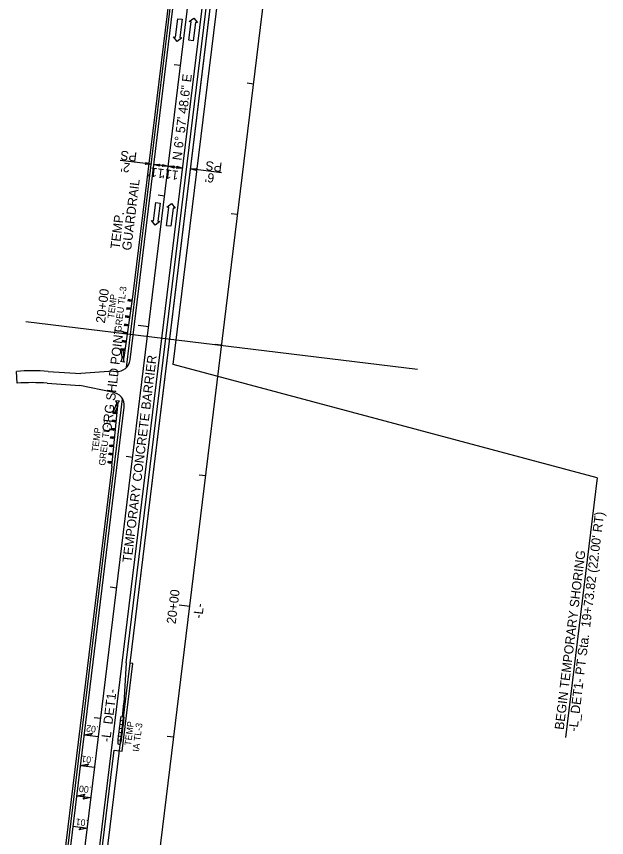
# Model space of a CAD drawing. Extents: x 473658 to 481584, y 489119 to 506230.
# Drawn here: x 481135 to 481584, y 489912 to 490536 of the extents above; entities that cross this region are included whole.
import ezdxf

# ---------------------------------------------------------------- set-up
doc = ezdxf.new("R2010")
doc.units = 0
for name, color, linetype in [('Exist Horizontal Alignment', 7, 'Continuous'), ('Exist Structure Minor Culvert Topo', 7, 'Continuous'), ('Exist Structure Minor Pipes CMP 60 Inch', 7, 'Continuous'), ('Exist Structure Minor Pipes RCP 12 Inch Leader', 7, 'Continuous'), ('Prop Conc Barrier', 7, 'Continuous'), ('Prop Dimension', 7, 'Continuous'), ('Prop EOT', 7, 'Continuous'), ('Prop Guardrail', 7, 'Continuous'), ('Prop Guardrail Anchor Unit CELL', 7, 'Continuous'), ('Prop Horizontal Alignment', 7, 'Continuous'), ('Prop Horizontal Alignment Direction Label', 7, 'Continuous'), ('Prop Horizontal Alignment Station Label', 7, 'Continuous'), ('Prop Horizontal Alignment Tick Label', 7, 'Continuous'), ('Prop Horizontal Alignment Tick Large', 7, 'Continuous'), ('Prop Horizontal Alignment Tick Small', 7, 'Continuous'), ('Prop Paved Shoulder', 7, 'Continuous'), ('Prop Shade Medium', 7, 'Continuous'), ('Prop Superelevation  Arrow CELL', 7, 'Continuous'), ('Prop Superelevation Label', 7, 'Continuous'), ('Scratch_Level_5', 7, 'Continuous'), ('Sheet Plan And Profile CELL', 7, 'Continuous'), ('Sheet Profile Grid Major CELL', 7, 'Continuous')]:
    doc.layers.add(name, color=color, linetype=linetype)

msp = doc.modelspace()

# ---------------------------------------------------------------- linework, layer by layer
at = {"layer": 'Exist Horizontal Alignment'}
for points in [[(481233.45, 490425.46), (481237.82, 490424.14), (481233.23, 490423.9), (481233.9, 490424.62)], [(481244.14, 490422.6), (481239.77, 490423.91), (481244.35, 490424.16), (481243.69, 490423.43)], [(481246.31, 490423.89), (481250.68, 490422.58), (481246.1, 490422.33), (481246.76, 490423.06)], [(481255.06, 490421.26), (481250.68, 490422.58), (481255.27, 490422.82), (481254.61, 490422.1)], [(481257.27, 490422.55), (481261.65, 490421.23), (481257.06, 490420.99), (481257.73, 490421.71)], [(481271.88, 490419.25), (481267.51, 490420.57), (481272.1, 490420.81), (481271.43, 490420.09)]]:
    msp.add_lwpolyline(points, close=True, dxfattribs=at)
at = {"layer": 'Exist Structure Minor Pipes CMP 60 Inch'}
msp.add_line((481254.45, 490271.98), (481344.18, 491006.64), dxfattribs=at)
at = {"layer": 'Exist Structure Minor Pipes RCP 12 Inch Leader'}
for p, q in [((481214.54, 490004.6), (481214.18, 490001.62)), ((481214.54, 490004.6), (481217.03, 490004.3)), ((481217.03, 490004.3), (481216.66, 490001.32)), ((481213.82, 489998.65), (481213.45, 489995.67)), ((481214.18, 490001.62), (481213.82, 489998.65)), ((481213.82, 489998.65), (481216.3, 489998.34)), ((481214.18, 490001.62), (481216.66, 490001.32)), ((481216.3, 489998.34), (481215.93, 489995.36)), ((481216.66, 490001.32), (481216.3, 489998.34)), ((481213.09, 489992.69), (481212.72, 489989.71)), ((481213.45, 489995.67), (481213.09, 489992.69)), ((481213.09, 489992.69), (481215.57, 489992.39)), ((481213.45, 489995.67), (481215.93, 489995.36)), ((481215.57, 489992.39), (481215.21, 489989.41)), ((481215.93, 489995.36), (481215.57, 489992.39)), ((481212.36, 489986.73), (481212.24, 489985.74)), ((481212.24, 489985.74), (481212.25, 489983.73)), ((481212.72, 489989.71), (481212.36, 489986.73)), ((481212.36, 489986.73), (481214.84, 489986.43)), ((481212.72, 489989.71), (481215.21, 489989.41)), ((481214.72, 489985.44), (481214.23, 489983.48)), ((481214.84, 489986.43), (481214.72, 489985.44)), ((481215.21, 489989.41), (481214.84, 489986.43)), ((481212.25, 489983.73), (481213.24, 489983.6)), ((481213.24, 489983.6), (481214.23, 489983.48))]:
    msp.add_line(p, q, dxfattribs=at)
at = {"layer": 'Prop Conc Barrier'}
for p, q in [((481218.72, 490045.39), (481336.24, 491007.62)), ((481218.72, 490045.39), (481217.03, 490014.62)), ((481215.78, 490004.45), (481217.03, 490014.62))]:
    msp.add_line(p, q, dxfattribs=at)
at = {"layer": 'Prop Dimension'}
for p, q in [((481237.78, 490424.16), (481214.22, 490427.03)), ((481261.6, 490421.23), (481239.77, 490423.91)), ((481291.01, 490417.64), (481267.51, 490420.57))]:
    msp.add_line(p, q, dxfattribs=at)
at = {"layer": 'Prop EOT'}
for p, q in [((481195.32, 489878.54), (481333.26, 491007.97)), ((481221.63, 490275.44), (481280.31, 490755.9)), ((481135.89, 490257.77), (481135.3, 490266.75)), ((481159.31, 490266.74), (481184.19, 490265.02)), ((481209.13, 490266.8), (481184.19, 490265.02)), ((481209.13, 490266.8), (481211.01, 490266.67)), ((481158.69, 490257.77), (481183.57, 490256.04)), ((481208.02, 490250.84), (481183.57, 490256.04)), ((481173.48, 489881.21), (481217.26, 490239.65))]:
    msp.add_line(p, q, dxfattribs=at)
for centre, radius, start, end in [((481211.7, 490276.65), 10, 266.04028, 353.03651), ((481147.26, 490092.66), 174.5, 86.04028, 93.92915), ((481147.26, 490092.66), 165.5, 86.04028, 93.93992), ((481207.33, 490240.87), 10, 353.03651, 86.04028)]:
    msp.add_arc(centre, radius, start, end, dxfattribs=at)
at = {"layer": 'Prop Guardrail'}
for p, q in [((481271.2, 490714.29), (481223.47, 490323.45)), ((481207.7, 490194.38), (481169.51, 489881.7))]:
    msp.add_line(p, q, dxfattribs=at)
at = {"layer": 'Prop Guardrail Anchor Unit CELL'}
for p, q in [((481223.47, 490323.45), (481216.87, 490277.16)), ((481220.14, 490321.35), (481220, 490320.36)), ((481220, 490320.36), (481221.62, 490321.14)), ((481223.11, 490320.93), (481220.14, 490321.35)), ((481221.48, 490320.15), (481220.14, 490321.35)), ((481221.62, 490321.14), (481221.48, 490320.15)), ((481221.48, 490320.15), (481223.11, 490320.93)), ((481221.62, 490321.14), (481222.97, 490319.94)), ((481223.11, 490320.93), (481222.97, 490319.94)), ((481219.2, 490315.12), (481219.05, 490314.13)), ((481219.05, 490314.13), (481220.71, 490314.91)), ((481222.22, 490314.69), (481219.2, 490315.12)), ((481220.57, 490313.92), (481219.2, 490315.12)), ((481222.97, 490319.94), (481220, 490320.36)), ((481220.71, 490314.91), (481220.57, 490313.92)), ((481222.22, 490314.69), (481220.57, 490313.92)), ((481220.71, 490314.91), (481222.08, 490313.7)), ((481222.97, 490319.94), (481221.48, 490320.15)), ((481218.31, 490308.88), (481218.17, 490307.89)), ((481218.17, 490307.89), (481219.82, 490308.67)), ((481221.33, 490308.45), (481218.31, 490308.88)), ((481219.68, 490307.68), (481218.31, 490308.88)), ((481222.08, 490313.7), (481219.05, 490314.13)), ((481219.82, 490308.67), (481219.68, 490307.68)), ((481221.33, 490308.45), (481219.68, 490307.68)), ((481219.82, 490308.67), (481221.19, 490307.46)), ((481217.43, 490302.64), (481217.29, 490301.65)), ((481217.29, 490301.65), (481218.94, 490302.43)), ((481220.44, 490302.22), (481217.43, 490302.64)), ((481218.8, 490301.44), (481217.43, 490302.64)), ((481221.19, 490307.46), (481218.17, 490307.89)), ((481218.94, 490302.43), (481218.8, 490301.44)), ((481220.44, 490302.22), (481218.8, 490301.44)), ((481218.94, 490302.43), (481220.3, 490301.23)), ((481220.44, 490302.22), (481220.3, 490301.23)), ((481216.44, 490296.42), (481216.3, 490295.43)), ((481216.3, 490295.43), (481218, 490296.2)), ((481219.55, 490295.98), (481216.44, 490296.42)), ((481217.86, 490295.21), (481216.44, 490296.42)), ((481220.3, 490301.23), (481217.29, 490301.65)), ((481218, 490296.2), (481217.86, 490295.21)), ((481219.55, 490295.98), (481217.86, 490295.21)), ((481218, 490296.2), (481219.41, 490294.99)), ((481215.69, 490290.16), (481215.55, 490289.17)), ((481215.55, 490289.17), (481217.18, 490289.95)), ((481218.66, 490289.74), (481215.69, 490290.16)), ((481217.04, 490288.96), (481215.69, 490290.16)), ((481219.41, 490294.99), (481216.3, 490295.43)), ((481217.18, 490289.95), (481217.04, 490288.96)), ((481218.66, 490289.74), (481217.04, 490288.96)), ((481217.18, 490289.95), (481218.52, 490288.75)), ((481214.74, 490283.93), (481214.6, 490282.94)), ((481214.6, 490282.94), (481216.26, 490283.72)), ((481217.77, 490283.5), (481214.74, 490283.93)), ((481216.12, 490282.73), (481214.74, 490283.93)), ((481218.52, 490288.75), (481215.55, 490289.17)), ((481216.26, 490283.72), (481216.12, 490282.73)), ((481217.77, 490283.5), (481216.12, 490282.73)), ((481216.26, 490283.72), (481217.63, 490282.51)), ((481217.63, 490282.51), (481214.6, 490282.94)), ((481214.6, 490282.94), (481215.46, 490277.87)), ((481215.46, 490277.87), (481215.31, 490276.88)), ((481215.31, 490276.88), (481216.94, 490277.66)), ((481215.33, 490275.26), (481215.58, 490277.29)), ((481215.46, 490277.87), (481215.39, 490277.38)), ((481216.94, 490277.66), (481215.46, 490277.87)), ((481216.8, 490276.67), (481215.46, 490277.87)), ((481215.58, 490277.29), (481216.19, 490277.22)), ((481216.12, 490282.73), (481216.94, 490277.66)), ((481216.19, 490277.22), (481216.79, 490277.14)), ((481216.79, 490277.14), (481216.54, 490275.11)), ((481214.33, 490274.2), (481215.33, 490275.26)), ((481217.25, 490273.84), (481214.33, 490274.2)), ((481216.8, 490276.67), (481215.31, 490276.88)), ((481216.54, 490275.11), (481217.25, 490273.84)), ((481207.7, 490194.38), (481212.44, 490240.89)), ((481208.85, 490235.83), (481210.9, 490240.55)), ((481210.37, 490235.68), (481212.39, 490240.4)), ((481213.61, 490244.03), (481210.69, 490244.38)), ((481210.69, 490244.38), (481211.4, 490243.11)), ((481210.9, 490240.55), (481211, 490241.54)), ((481212.49, 490241.39), (481210.9, 490240.55)), ((481210.9, 490240.55), (481210.95, 490241.05)), ((481212.39, 490240.4), (481210.9, 490240.55)), ((481212.49, 490241.39), (481211, 490241.54)), ((481211, 490241.54), (481212.39, 490240.4)), ((481211.4, 490243.11), (481211.16, 490241.08)), ((481211.16, 490241.08), (481211.76, 490241.01)), ((481211.76, 490241.01), (481212.37, 490240.93)), ((481212.37, 490240.93), (481212.61, 490242.97)), ((481212.61, 490242.97), (481213.61, 490244.03)), ((481208.74, 490234.84), (481208.85, 490235.83)), ((481210.37, 490235.68), (481208.74, 490234.84)), ((481211.79, 490234.53), (481208.74, 490234.84)), ((481211.89, 490235.52), (481208.85, 490235.83)), ((481208.85, 490235.83), (481210.27, 490234.68)), ((481210.27, 490234.68), (481210.37, 490235.68)), ((481210.27, 490234.68), (481211.89, 490235.52)), ((481211.79, 490234.53), (481210.37, 490235.68)), ((481208.17, 490228.56), (481208.27, 490229.56)), ((481209.76, 490229.4), (481208.17, 490228.56)), ((481211.15, 490228.26), (481208.17, 490228.56)), ((481211.25, 490229.25), (481208.27, 490229.56)), ((481208.27, 490229.56), (481209.66, 490228.41)), ((481209.66, 490228.41), (481209.76, 490229.4)), ((481209.66, 490228.41), (481211.25, 490229.25)), ((481211.15, 490228.26), (481209.76, 490229.4)), ((481207.39, 490222.31), (481207.49, 490223.3)), ((481209.06, 490223.14), (481207.39, 490222.31)), ((481210.51, 490221.99), (481207.39, 490222.31)), ((481210.62, 490222.98), (481207.49, 490223.3)), ((481207.49, 490223.3), (481208.95, 490222.15)), ((481208.95, 490222.15), (481209.06, 490223.14)), ((481208.95, 490222.15), (481210.62, 490222.98)), ((481210.51, 490221.99), (481209.06, 490223.14)), ((481206.86, 490216.03), (481206.96, 490217.02)), ((481208.47, 490216.87), (481206.86, 490216.03)), ((481209.88, 490215.72), (481206.86, 490216.03)), ((481209.98, 490216.71), (481206.96, 490217.02)), ((481206.96, 490217.02), (481208.37, 490215.87)), ((481208.37, 490215.87), (481208.47, 490216.87)), ((481208.37, 490215.87), (481209.98, 490216.71)), ((481209.88, 490215.72), (481208.47, 490216.87)), ((481209.88, 490215.72), (481209.98, 490216.71)), ((481206.2, 490209.76), (481206.31, 490210.75)), ((481207.82, 490210.6), (481206.2, 490209.76)), ((481209.24, 490209.45), (481206.2, 490209.76)), ((481209.34, 490210.44), (481206.31, 490210.75)), ((481206.31, 490210.75), (481207.72, 490209.6)), ((481207.72, 490209.6), (481207.82, 490210.6)), ((481207.72, 490209.6), (481209.34, 490210.44)), ((481209.24, 490209.45), (481207.82, 490210.6)), ((481205.56, 490203.49), (481205.66, 490204.49)), ((481207.18, 490204.33), (481205.56, 490203.49)), ((481208.6, 490203.18), (481205.56, 490203.49)), ((481208.7, 490204.18), (481205.66, 490204.49)), ((481205.66, 490204.49), (481207.08, 490203.34)), ((481207.08, 490203.34), (481207.18, 490204.33)), ((481207.08, 490203.34), (481208.7, 490204.18)), ((481208.6, 490203.18), (481207.18, 490204.33)), ((481204.98, 490197.22), (481205.08, 490198.21)), ((481206.57, 490198.06), (481204.98, 490197.22)), ((481207.96, 490196.91), (481204.98, 490197.22)), ((481208.06, 490197.91), (481205.08, 490198.21)), ((481205.08, 490198.21), (481206.47, 490197.06)), ((481206.47, 490197.06), (481206.57, 490198.06)), ((481206.47, 490197.06), (481208.06, 490197.91)), ((481208.06, 490197.91), (481206.57, 490198.06)), ((481206.57, 490198.06), (481207.96, 490196.91)), ((481207.96, 490196.91), (481208.06, 490197.91))]:
    msp.add_line(p, q, dxfattribs=at)
at = {"layer": 'Prop Horizontal Alignment'}
for p, q in [((481200.24, 489541.46), (481402.27, 491195.58)), ((481184.4, 489879.88), (481322.35, 491009.3))]:
    msp.add_line(p, q, dxfattribs=at)
at = {"layer": 'Prop Horizontal Alignment Station Label'}
for q in [(481254.45, 490271.98), (481552.56, 489988.45)]:
    msp.add_line((481576.67, 490185.87), q, dxfattribs=at)
at = {"layer": 'Prop Horizontal Alignment Tick Large'}
for p, q in [((481235.79, 490300.64), (481227.85, 490301.61)), ((481266.99, 490088.04), (481259.05, 490089.01))]:
    msp.add_line(p, q, dxfattribs=at)
at = {"layer": 'Prop Horizontal Alignment Tick Small'}
for p, q in [((481260.04, 490499.16), (481255.07, 490499.77)), ((481315.49, 490485.09), (481310.53, 490485.7)), ((481247.91, 490399.9), (481242.95, 490400.51)), ((481303.36, 490385.83), (481298.4, 490386.43)), ((481291.24, 490286.57), (481286.28, 490287.17)), ((481223.67, 490201.37), (481218.7, 490201.98)), ((481279.12, 490187.3), (481274.15, 490187.91)), ((481211.54, 490102.11), (481206.58, 490102.72)), ((481199.42, 490002.85), (481194.46, 490003.46)), ((481254.87, 489988.78), (481249.91, 489989.39))]:
    msp.add_line(p, q, dxfattribs=at)
at = {"layer": 'Prop Paved Shoulder'}
for p, q in [((481221.7, 490045.03), (481339.22, 491007.26)), ((481218.92, 490269.72), (481279.63, 490766.83)), ((481171.5, 489881.45), (481216, 490245.85)), ((481215.55, 489978.22), (481223.68, 490044.78)), ((481223.68, 490044.78), (481221.7, 490045.03)), ((481197.3, 489878.3), (481209.6, 489978.94)), ((481209.6, 489978.94), (481215.55, 489978.22))]:
    msp.add_line(p, q, dxfattribs=at)
at = {"layer": 'Prop Shade Medium'}
for p, q in [((481256.21, 490520.8), (481258, 490534.69)), ((481258, 490534.69), (481261.27, 490534.27)), ((481261.27, 490534.27), (481259.48, 490520.38)), ((481266.67, 490532.5), (481270.14, 490535.23)), ((481270.14, 490535.23), (481272.91, 490531.7)), ((481266.36, 490518.43), (481268.15, 490532.31)), ((481268.15, 490532.31), (481266.67, 490532.5)), ((481271.43, 490531.89), (481269.64, 490518.01)), ((481272.91, 490531.7), (481271.43, 490531.89)), ((481257.49, 490517.46), (481254.72, 490520.99)), ((481254.72, 490520.99), (481256.21, 490520.8)), ((481260.97, 490520.19), (481257.49, 490517.46)), ((481259.48, 490520.38), (481260.97, 490520.19)), ((481269.64, 490518.01), (481266.36, 490518.43)), ((481239.44, 490381.18), (481241.23, 490395.06)), ((481241.23, 490395.06), (481244.5, 490394.64)), ((481244.5, 490394.64), (481242.71, 490380.75)), ((481249.42, 490377.4), (481251.21, 490391.29)), ((481249.72, 490391.48), (481253.2, 490394.21)), ((481251.21, 490391.29), (481249.72, 490391.48)), ((481254.48, 490390.86), (481252.69, 490376.98)), ((481253.2, 490394.21), (481255.97, 490390.67)), ((481255.97, 490390.67), (481254.48, 490390.86)), ((481240.72, 490377.83), (481237.95, 490381.37)), ((481237.95, 490381.37), (481239.44, 490381.18)), ((481244.2, 490380.56), (481240.72, 490377.83)), ((481242.71, 490380.75), (481244.2, 490380.56)), ((481252.69, 490376.98), (481249.42, 490377.4))]:
    msp.add_line(p, q, dxfattribs=at)
at = {"layer": 'Prop Superelevation  Arrow CELL'}
for points in [[(481186.83, 489990.54), (481193.03, 489991.8), (481191.43, 489989.98)], [(481184.01, 489967.39), (481190.2, 489968.64), (481188.6, 489966.83)], [(481181.18, 489944.23), (481187.38, 489945.49), (481185.77, 489943.67)], [(481192.1, 489942.89), (481185.9, 489941.64), (481187.51, 489943.46)], [(481189.27, 489919.74), (481183.07, 489918.48), (481184.68, 489920.3)]]:
    msp.add_lwpolyline(points, close=True, dxfattribs=at)
at = {"layer": 'Prop Superelevation Label'}
for p, q in [((481186.83, 489990.54), (481197.75, 489989.21)), ((481184.01, 489967.39), (481194.93, 489966.05)), ((481181.18, 489944.23), (481192.1, 489942.89)), ((481178.35, 489921.07), (481189.27, 489919.74))]:
    msp.add_line(p, q, dxfattribs=at)
at = {"layer": 'Scratch_Level_5'}
msp.add_line((481201.27, 489877.82), (481339.22, 491007.24), dxfattribs=at)
at = {"layer": 'Sheet Plan And Profile CELL'}
msp.add_line((481142.35, 490304.75), (481440.13, 490268.38), dxfattribs=at)

# ---------------------------------------------------------------- texts
at = {"layer": 'Exist Structure Minor Culvert Topo'}
for s, p in [('GREU TL-3', (481214.81, 490296.32)), ('TEMP', (481209.47, 490306.66)), ('GREU TL-3', (481202.71, 490194.93)), ('TEMP', (481197.37, 490205.27)), ('TEMP', (481222.37, 489982.07)), ('IA TL-3', (481228.42, 489977.5))]:
    msp.add_text(s, height=5, rotation=83.03651, dxfattribs=at).set_placement(p)
at = {"layer": 'Prop Horizontal Alignment Direction Label'}
for s, p in [('N 6%%d 57\' 48.6" E', (481260.66, 490426.73)), ('-L-', (481276.52, 490078.66)), ('-L_DET1-', (481206.55, 489984.78))]:
    msp.add_text(s, height=7, rotation=83.03651, dxfattribs=at).set_placement(p)
at = {"layer": 'Prop Horizontal Alignment Station Label'}
for s, p in [("-L_DET1- PT Sta.  19+73.82 (22.00' RT)", (481561.56, 489992.84)), ('BEGIN TEMPORARY SHORING', (481551.14, 489994.11))]:
    msp.add_text(s, height=7, rotation=83.03651, dxfattribs=at).set_placement(p)
at = {"layer": 'Prop Horizontal Alignment Tick Label'}
for p in [(481202.53, 490302.99), (481256.27, 490074.47)]:
    msp.add_text('20+00', height=7, rotation=83.03651, dxfattribs=at).set_placement(p)
at = {"layer": 'Prop Superelevation  Arrow CELL'}
for s, p in [('.02', (481197.83, 489996.94)), ('.01', (481194.22, 489973.66)), ('.00', (481192.39, 489951.09)), ('.01', (481189.9, 489925.89))]:
    msp.add_text(s, height=5, rotation=173.03651, dxfattribs=at).set_placement(p)
at = {"layer": 'Scratch_Level_5'}
msp.add_text('ORG SHLD POINT', height=7, rotation=83.03983, dxfattribs=at).set_placement((481207.31, 490220.34))
at = {"layer": 'Sheet Profile Grid Major CELL'}
for s, rotation, p in [('PS', 173.03651, (481227.22, 490433.03)), ("2'", 173.03651, (481221.99, 490424.73)), ("11'", 173.03651, (481247.95, 490420.36)), ('PS', 173.03651, (481291.93, 490425.12)), ("11'", 173.03651, (481258.87, 490419.02)), ("6'", 173.03651, (481286.03, 490416.9)), ('GUARDRAIL', 83.03651, (481222.41, 490358.32)), ('TEMP.', 83.03651, (481213.6, 490359.4)), ('TEMPORARY CONCRETE BARRIER', 83.03651, (481222.74, 490121.2))]:
    msp.add_text(s, height=7, rotation=rotation, dxfattribs=at).set_placement(p)

doc.saveas('drawing.dxf')
